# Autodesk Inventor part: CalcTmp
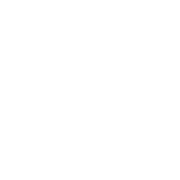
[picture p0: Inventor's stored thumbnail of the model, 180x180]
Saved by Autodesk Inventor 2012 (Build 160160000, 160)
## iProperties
Created: 2001-02
Part Number: CalcTmp
Document SubType Name: Modeling
Designer: Mila
Density: 1 g/cm^3
Material: Default
Company: CAD-Verlag
+MSCProtocol1+ProtocolID: P00040914104829119
+MSCProtocol2+Protocol: P00040914104829119<@PID>[Version]<@EL>Version=2.2<@EL>[Files]<@EL>DataFile=SpiData|THRJOIN<@EL>[Synchronize]<@EL>ChangedVars=<@EL>[Calc]<@EL>ScnVisible=1<@EL>Wi
+MSCProtocol3+ObjType: Calc
Control State: 0
Master: False
Checked Out: False
Shininess: 20.0
Length Units: 11269
Angle Units: 11279
Time Units: 11290
Mass Units: 11283
Length Display Precision: 3
Angle Display Precision: 2
Density: 0.0
Volumn: 0.0
Area: 0.0
PropertySet Name: Model Information
Author: Jürgen Kronas
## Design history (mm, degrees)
sketch "Sketch1"
  geometry: L1 (0, 0)-(0, 19.803); A1 r 9.932 centre (0.781, 9.901) between (0, 0) and (0, 19.803)
  constraints: 2 end point, 2 point on circle, 1 centre point, 1 vertical
  dimensions: "d0" = 90 deg dimension on L1.start L1.end L1 A1.centre A1
revolve "Revolution1" sketch "Sketch1" stored, may be unused: angle "d0" = 90 deg
node "Volumenkörper1"
node "Volumenkörpern"
node "Oberflächenkörpern"
